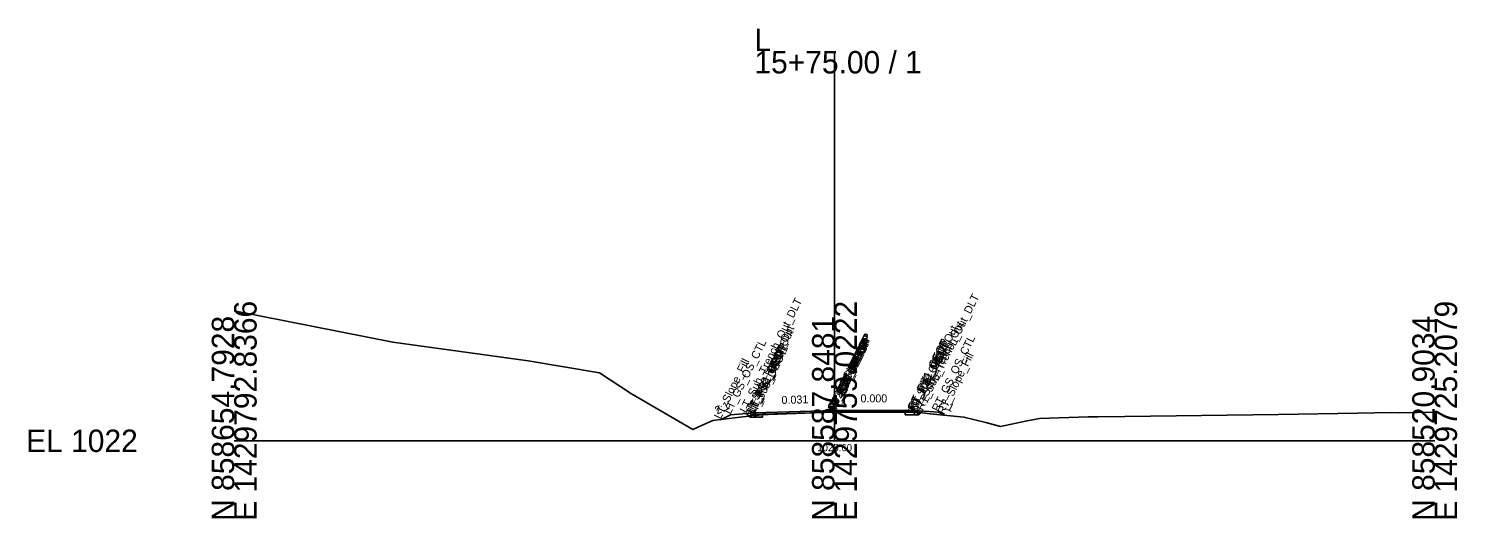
# Model space of a CAD drawing. Extents: x -26 to 153, y -10 to 13058.
# Drawn here: x -25.7 to 152.8, y 8490.3 to 8551.5 of the extents above; entities that cross this region are included whole.
import ezdxf

# ---------------------------------------------------------------- set-up
doc = ezdxf.new("R2010")
doc.units = 0
for name, color, linetype in [('Default', 7, 'Continuous'), ('Exist Cross Section Cell', 7, 'Continuous'), ('Exist XS Ground Line', 7, 'Continuous'), ('Prop CMT Pvmt Course 1', 7, 'Continuous'), ('Prop CMT Pvmt Course 2', 7, 'Continuous'), ('Prop CMT Pvmt Surface', 7, 'Continuous'), ('Prop CMT Pvmt Surface Shoulder', 7, 'Continuous'), ('Prop CMT Pvmt Wedge Surface 2', 7, 'Continuous'), ('Prop CMT Shld Paved Course 1', 7, 'Continuous'), ('Prop CMT Shld Paved Course 2', 7, 'Continuous'), ('Prop CMT Slope Grass', 7, 'Continuous'), ('Prop CMT Subgrade Daylight Point', 7, 'Continuous'), ('Prop CMT Subgrade Earthwork', 7, 'Continuous'), ('Prop XS Dump Level', 7, 'Continuous'), ('Prop XS SE Text', 7, 'Continuous'), ('Prop XS Side Slope Text', 7, 'Continuous')]:
    doc.layers.add(name, color=color, linetype=linetype)

msp = doc.modelspace()

# ---------------------------------------------------------------- linework, layer by layer
at = {"layer": 'Exist Cross Section Cell'}
for p, q in [((75, 8500), (75, 8548.68)), ((0, 8500), (75, 8500)), ((75, 8500), (150, 8500))]:
    msp.add_line(p, q, dxfattribs=at)
at = {"layer": 'Exist XS Ground Line'}
msp.add_lwpolyline([(0, 8516.23), (19.84, 8512.31), (36.74, 8509.98), (45.63, 8508.5), (49.66, 8505.86), (57.29, 8501.41), (58.31, 8501.89), (59.82, 8502.52), (64.59, 8503.1), (65.26, 8503.18), (66.03, 8503.27), (66.71, 8503.3), (74.78, 8503.59), (75.68, 8503.61), (83.85, 8503.84), (86.01, 8503.49), (86.95, 8503.37), (91.17, 8502.97), (93.93, 8502.27), (95.76, 8501.8), (98.89, 8502.46), (100.6, 8502.77), (106.69, 8503.01), (107.89, 8503.01), (111.3, 8503.04), (130.48, 8503.29), (140.37, 8503.47), (144.59, 8503.53), (145.61, 8503.5), (150, 8503.59)], dxfattribs=at)
at = {"layer": 'Prop CMT Pvmt Course 1'}
for points in [[(75, 8503.8), (65, 8503.48)], [(75, 8503.59), (66.03, 8503.31)], [(75, 8503.59), (75, 8503.8)], [(75, 8503.8), (85, 8503.8)], [(75, 8503.59), (75, 8503.8)], [(75, 8503.59), (83.85, 8503.59)], [(85, 8503.59), (83.85, 8503.59)], [(85, 8503.8), (85, 8503.59)], [(65, 8503.48), (65, 8503.28)], [(65, 8503.28), (66.03, 8503.31)]]:
    msp.add_lwpolyline(points, dxfattribs=at)
msp.add_lwpolyline([(75, 8503.59), (75, 8503.67), (75, 8503.67), (75, 8503.59)], close=True, dxfattribs=at)
msp.add_lwpolyline([(75, 8503.59), (75, 8503.67), (75, 8503.67), (75, 8503.59)], close=True, dxfattribs=at)
at = {"layer": 'Prop CMT Pvmt Course 2'}
for points in [[(83.85, 8503.26), (83.85, 8503.59)], [(85, 8503.59), (85, 8503.26)], [(65, 8503.28), (65, 8502.94)], [(65, 8502.94), (66.03, 8502.97)], [(66.03, 8502.97), (66.03, 8503.31)], [(85, 8503.26), (83.85, 8503.26)]]:
    msp.add_lwpolyline(points, dxfattribs=at)
at = {"layer": 'Prop CMT Pvmt Surface'}
for points in [[(75, 8503.8), (65, 8503.48)], [(75, 8503.8), (85, 8503.8)]]:
    msp.add_lwpolyline(points, dxfattribs=at)
at = {"layer": 'Prop CMT Pvmt Surface Shoulder'}
for points in [[(85, 8503.8), (85, 8503.8)], [(65, 8503.48), (65, 8503.48)]]:
    msp.add_lwpolyline(points, dxfattribs=at)
at = {"layer": 'Prop CMT Pvmt Wedge Surface 2'}
for points in [[(75, 8503.59), (65, 8503.28)], [(75, 8503.59), (85, 8503.59)]]:
    msp.add_lwpolyline(points, dxfattribs=at)
at = {"layer": 'Prop CMT Shld Paved Course 1'}
for points in [[(85, 8503.8), (85, 8503.8)], [(85, 8503.8), (85.21, 8503.58)], [(85, 8503.59), (85, 8503.8)], [(85.21, 8503.58), (85, 8503.59)], [(65, 8503.48), (64.79, 8503.27)], [(64.79, 8503.27), (65, 8503.28)], [(65, 8503.48), (65, 8503.48)], [(65, 8503.28), (65, 8503.48)]]:
    msp.add_lwpolyline(points, dxfattribs=at)
at = {"layer": 'Prop CMT Shld Paved Course 2'}
for points in [[(85, 8503.59), (85.21, 8503.58)], [(85, 8503.26), (85, 8503.59)], [(85.21, 8503.58), (85.21, 8503.58)], [(85.21, 8503.58), (85.55, 8503.24)], [(64.79, 8503.27), (64.45, 8502.93)], [(64.45, 8502.93), (65, 8502.94)], [(65, 8503.28), (64.79, 8503.27)], [(64.79, 8503.27), (64.79, 8503.27)], [(65, 8502.94), (65, 8503.28)], [(85.55, 8503.24), (85, 8503.26)]]:
    msp.add_lwpolyline(points, dxfattribs=at)
at = {"layer": 'Prop CMT Slope Grass'}
for points in [[(85, 8503.8), (88, 8503.56), (88.7, 8503.2)], [(65, 8503.48), (62, 8503.24), (60.78, 8502.63)]]:
    msp.add_lwpolyline(points, dxfattribs=at)
at = {"layer": 'Prop CMT Subgrade Earthwork'}
for p, q in [((83.85, 8503.84), (83.85, 8503.26)), ((66.03, 8503.27), (66.03, 8502.97))]:
    msp.add_line(p, q, dxfattribs=at)
for points in [[(85.55, 8503.24), (86.02, 8503.71)], [(64.45, 8502.93), (63.98, 8503.4)], [(65, 8502.94), (64.45, 8502.93)], [(66.03, 8502.97), (65, 8502.94)], [(83.85, 8503.26), (85, 8503.26)], [(85, 8503.26), (85.55, 8503.24)]]:
    msp.add_lwpolyline(points, dxfattribs=at)

# ---------------------------------------------------------------- texts
at = {"layer": 'Default'}
msp.add_text('-', height=0.0001, dxfattribs=at).set_placement((0, 8500))
at = {"layer": 'Exist Cross Section Cell'}
for s, p in [('L', (65, 8548.68)), ('15+75.00 / 1', (65, 8545.88)), ('EL 1022', (-26, 8498.6))]:
    msp.add_text(s, height=2.8, dxfattribs=at).set_placement(p)
for s, p in [('E 1429792.8366', (2.8, 8490)), ('E 1429759.0222', (77.8, 8490)), ('E 1429725.2079', (152.8, 8490)), ('N 858654.7928', (0, 8490)), ('N 858587.8481', (75, 8490)), ('N 858520.9034', (150, 8490))]:
    msp.add_text(s, height=2.8, rotation=90, dxfattribs=at).set_placement(p)
at = {"layer": 'Prop CMT Subgrade Daylight Point'}
msp.add_text('1025.60', height=0.9, dxfattribs=at).set_placement((72.85, 8498.7))
at = {"layer": 'Prop XS Dump Level'}
for s, p in [('LT_Sub_Trench_Out_DLT', (63.98, 8503.4)), ('RT_Sub_Trench_Out_DLT', (86.02, 8503.71)), ('LT_Sub_Trench_Out', (64.45, 8502.93)), ('RT_PS2_Shelf_Out', (85.21, 8503.58)), ('RT_Sub_Trench_Out', (85.55, 8503.24)), ('LT_PS2_Shelf_Out', (64.79, 8503.27)), ('RT_PV1_OEEOP', (75, 8503.67)), ('RT_PV2_OEEOP', (75, 8503.59)), ('LT_PV1_OEEOP', (75, 8503.67)), ('LT_PV2_OEEOP', (75, 8503.59)), ('RT_Sub_OEEOP', (75, 8503.26)), ('RT_PV1_IEEOP', (75, 8503.67)), ('RT_PV2_IEEOP', (75, 8503.59)), ('LT_Sub_OEEOP', (75, 8503.26)), ('LT_PV1_IEEOP', (75, 8503.67)), ('LT_PV2_IEEOP', (75, 8503.59)), ('RT_PV1_OEOT', (85, 8503.8)), ('RT_PS1_OEOP', (85, 8503.8)), ('RT_PV2_OEOT', (85, 8503.59)), ('RT_PS2_OEOP', (85.21, 8503.58)), ('RT_GS_OS_CTL', (88, 8503.56)), ('LT_GS_OS_CTL', (62, 8503.24)), ('LT_PS2_OEOP', (64.79, 8503.27)), ('LT_PV1_OEOT', (65, 8503.48)), ('LT_PS1_OEOP', (65, 8503.48)), ('LT_PV2_OEOT', (65, 8503.28)), ('LT_Sub_OEOT', (65, 8502.94)), ('RT_Sub_OEOT', (85, 8503.26)), ('RT_Slope_Fill', (88.7, 8503.2)), ('LT_Slope_Fill', (60.78, 8502.63)), ('PV1_PGL', (75, 8503.8)), ('PV2_PGL', (75, 8503.59))]:
    msp.add_text(s, height=1, rotation=63.5833, dxfattribs=at).set_placement(p)
at = {"layer": 'Prop XS SE Text'}
for s, rotation, p in [('0.031', 1.7947, (68.4, 8504.59)), ('0.000', 0, (78.25, 8504.8))]:
    msp.add_text(s, height=1, rotation=rotation, dxfattribs=at).set_placement(p)
at = {"layer": 'Prop XS Side Slope Text'}
for rotation, p in [(26.5651, (60.35, 8503.26)), (333.4349, (87.98, 8504.41))]:
    msp.add_text('2:1', height=1, rotation=rotation, dxfattribs=at).set_placement(p)

doc.saveas('drawing.dxf')
